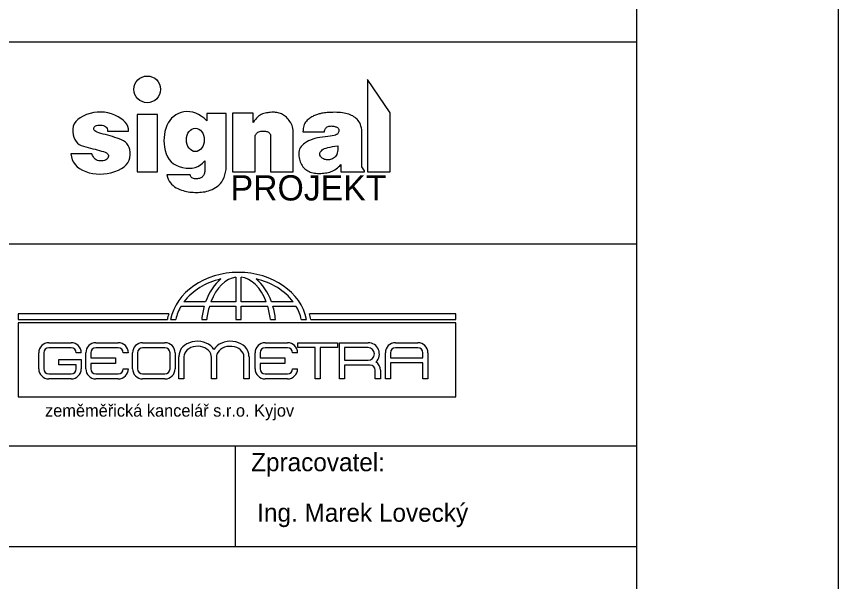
# Model space of a CAD drawing. Extents: x 1983 to 3683, y -1637 to -1193.
# Drawn here: x 2856.3 to 2937.6, y -1538.2 to -1482.2 of the extents above; entities that cross this region are included whole.
import ezdxf

# ---------------------------------------------------------------- set-up
doc = ezdxf.new("R2010")
doc.units = 0
for name, color, linetype in [('Default', 7, 'Continuous'), ('Komunikace', 7, 'Continuous'), ('Křížky', 7, 'Continuous'), ('Svazek obcí-chráničky', 7, 'Continuous'), ('Vrstva 51', 7, 'Continuous')]:
    doc.layers.add(name, color=color, linetype=linetype)

msp = doc.modelspace()

# ---------------------------------------------------------------- linework, layer by layer
at = {"layer": 'Default'}
msp.add_lwpolyline([(2727.602, -1636.746), (2937.602, -1636.746), (2937.602, -1339.746), (2727.602, -1339.746)], close=True, dxfattribs=at)
at = {"layer": 'Komunikace'}
for points in [[(2893.266, -1497.626), (2893.266, -1491.786), (2891.026, -1488.506), (2891.026, -1497.626), (2893.266, -1497.626)], [(2864.538, -1497.86), (2864.9, -1497.844), (2865.266, -1497.796), (2865.637, -1497.717), (2866.013, -1497.607), (2866.368, -1497.471), (2866.676, -1497.315), (2866.937, -1497.139), (2867.151, -1496.943), (2867.318, -1496.727), (2867.439, -1496.491), (2867.512, -1496.235), (2867.539, -1495.959), (2867.528, -1495.685), (2867.49, -1495.437), (2867.424, -1495.212), (2867.33, -1495.013), (2867.209, -1494.838), (2867.059, -1494.688), (2866.882, -1494.563), (2866.678, -1494.462), (2866.458, -1494.376), (2866.236, -1494.294), (2866.012, -1494.217), (2865.786, -1494.144), (2865.557, -1494.075), (2865.326, -1494.011), (2865.092, -1493.952), (2864.857, -1493.896), (2864.635, -1493.841), (2864.444, -1493.782), (2864.283, -1493.719), (2864.153, -1493.652), (2864.053, -1493.581), (2863.983, -1493.506), (2863.944, -1493.427), (2863.936, -1493.343), (2863.952, -1493.264), (2863.989, -1493.195), (2864.045, -1493.137), (2864.121, -1493.09), (2864.217, -1493.053), (2864.332, -1493.028), (2864.468, -1493.013), (2864.623, -1493.01), (2864.778, -1493.021), (2864.914, -1493.05), (2865.029, -1493.097), (2865.123, -1493.163), (2865.198, -1493.247), (2865.253, -1493.349), (2865.287, -1493.469), (2865.302, -1493.608), (2867.381, -1493.608), (2867.361, -1493.366), (2867.299, -1493.136), (2867.194, -1492.919), (2867.046, -1492.715), (2866.856, -1492.523), (2866.622, -1492.345), (2866.345, -1492.179), (2866.026, -1492.025), (2865.684, -1491.896), (2865.339, -1491.801), (2864.991, -1491.741), (2864.641, -1491.717), (2864.288, -1491.727), (2863.932, -1491.771), (2863.574, -1491.851), (2863.213, -1491.966), (2862.875, -1492.108), (2862.586, -1492.271), (2862.345, -1492.454), (2862.153, -1492.658), (2862.009, -1492.882), (2861.915, -1493.127), (2861.868, -1493.393), (2861.871, -1493.679), (2861.91, -1493.96), (2861.976, -1494.212), (2862.069, -1494.434), (2862.187, -1494.627), (2862.332, -1494.791), (2862.503, -1494.924), (2862.7, -1495.029), (2862.923, -1495.103), (2863.158, -1495.163), (2863.389, -1495.223), (2863.617, -1495.282), (2863.841, -1495.341), (2864.061, -1495.4), (2864.278, -1495.458), (2864.491, -1495.516), (2864.701, -1495.574), (2864.893, -1495.634), (2865.054, -1495.698), (2865.185, -1495.767), (2865.284, -1495.841), (2865.353, -1495.918), (2865.391, -1496.001), (2865.398, -1496.088), (2865.374, -1496.179), (2865.327, -1496.267), (2865.266, -1496.343), (2865.191, -1496.408), (2865.101, -1496.461), (2864.997, -1496.503), (2864.878, -1496.533), (2864.745, -1496.551), (2864.598, -1496.558), (2864.45, -1496.547), (2864.314, -1496.514), (2864.19, -1496.458), (2864.079, -1496.38), (2863.98, -1496.279), (2863.894, -1496.155), (2863.82, -1496.008), (2863.758, -1495.84), (2861.678, -1495.84), (2861.722, -1496.147), (2861.805, -1496.429), (2861.928, -1496.687), (2862.091, -1496.92), (2862.293, -1497.13), (2862.535, -1497.315), (2862.816, -1497.476), (2863.137, -1497.613), (2863.48, -1497.722), (2863.828, -1497.799), (2864.181, -1497.846), (2864.538, -1497.86)], [(2870.226, -1497.626), (2870.226, -1491.946), (2868.226, -1491.946), (2868.226, -1497.626), (2870.226, -1497.626)], [(2874.086, -1499.668), (2874.254, -1499.664), (2874.424, -1499.656), (2874.596, -1499.642), (2874.77, -1499.624), (2874.944, -1499.597), (2875.118, -1499.558), (2875.292, -1499.507), (2875.465, -1499.443), (2875.638, -1499.368), (2875.811, -1499.28), (2875.984, -1499.181), (2876.156, -1499.069), (2876.32, -1498.939), (2876.469, -1498.786), (2876.601, -1498.611), (2876.718, -1498.412), (2876.819, -1498.19), (2876.904, -1497.945), (2876.973, -1497.677), (2877.026, -1497.386), (2877.026, -1491.866), (2875.106, -1491.866), (2875.106, -1492.586), (2874.84, -1492.331), (2874.57, -1492.118), (2874.295, -1491.946), (2874.016, -1491.815), (2873.733, -1491.725), (2873.446, -1491.676), (2873.154, -1491.669), (2872.858, -1491.702), (2872.571, -1491.77), (2872.306, -1491.867), (2872.062, -1491.992), (2871.84, -1492.146), (2871.64, -1492.329), (2871.462, -1492.539), (2871.306, -1492.779), (2871.171, -1493.047), (2871.06, -1493.333), (2870.975, -1493.626), (2870.916, -1493.926), (2870.883, -1494.233), (2870.876, -1494.548), (2870.895, -1494.869), (2870.94, -1495.198), (2871.011, -1495.534), (2871.111, -1495.858), (2871.243, -1496.148), (2871.409, -1496.406), (2871.607, -1496.632), (2871.838, -1496.825), (2872.101, -1496.985), (2872.397, -1497.112), (2872.726, -1497.207), (2873.062, -1497.265), (2873.381, -1497.282), (2873.681, -1497.259), (2873.964, -1497.195), (2874.229, -1497.09), (2874.477, -1496.944), (2874.707, -1496.758), (2874.918, -1496.531), (2874.918, -1497.608), (2874.9, -1497.696), (2874.877, -1497.777), (2874.849, -1497.853), (2874.817, -1497.923), (2874.781, -1497.988), (2874.74, -1498.047), (2874.694, -1498.1), (2874.644, -1498.147), (2874.588, -1498.189), (2874.526, -1498.225), (2874.456, -1498.256), (2874.379, -1498.281), (2874.295, -1498.302), (2874.204, -1498.316), (2874.106, -1498.326), (2874.001, -1498.33), (2873.897, -1498.324), (2873.804, -1498.306), (2873.72, -1498.274), (2873.647, -1498.229), (2873.584, -1498.171), (2873.532, -1498.099), (2873.489, -1498.014), (2873.457, -1497.916), (2871.15, -1497.916), (2871.219, -1498.144), (2871.302, -1498.352), (2871.399, -1498.542), (2871.51, -1498.714), (2871.635, -1498.867), (2871.773, -1499), (2871.926, -1499.116), (2872.092, -1499.212), (2872.264, -1499.295), (2872.435, -1499.369), (2872.604, -1499.435), (2872.772, -1499.492), (2872.938, -1499.54), (2873.103, -1499.58), (2873.266, -1499.611), (2873.428, -1499.634), (2873.59, -1499.65), (2873.753, -1499.66), (2873.919, -1499.667), (2874.086, -1499.668)], [(2883.666, -1497.626), (2883.666, -1493.826), (2883.663, -1493.656), (2883.649, -1493.492), (2883.624, -1493.336), (2883.589, -1493.186), (2883.543, -1493.042), (2883.486, -1492.905), (2883.418, -1492.775), (2883.339, -1492.651), (2883.254, -1492.535), (2883.167, -1492.427), (2883.078, -1492.327), (2882.987, -1492.235), (2882.894, -1492.152), (2882.799, -1492.077), (2882.702, -1492.01), (2882.603, -1491.951), (2882.501, -1491.9), (2882.395, -1491.855), (2882.284, -1491.818), (2882.169, -1491.787), (2882.049, -1491.764), (2881.926, -1491.747), (2881.798, -1491.738), (2881.666, -1491.735), (2881.532, -1491.738), (2881.399, -1491.746), (2881.268, -1491.759), (2881.138, -1491.777), (2881.009, -1491.8), (2880.881, -1491.828), (2880.754, -1491.861), (2880.629, -1491.898), (2880.505, -1491.947), (2880.384, -1492.011), (2880.265, -1492.093), (2880.149, -1492.19), (2880.034, -1492.305), (2879.923, -1492.435), (2879.813, -1492.582), (2879.706, -1492.746), (2879.706, -1491.826), (2877.666, -1491.826), (2877.666, -1497.626), (2879.906, -1497.626), (2879.906, -1494.066), (2879.941, -1493.975), (2879.985, -1493.894), (2880.039, -1493.823), (2880.104, -1493.762), (2880.178, -1493.711), (2880.262, -1493.67), (2880.356, -1493.639), (2880.46, -1493.617), (2880.566, -1493.604), (2880.666, -1493.598), (2880.762, -1493.597), (2880.852, -1493.602), (2880.937, -1493.614), (2881.017, -1493.631), (2881.091, -1493.655), (2881.16, -1493.685), (2881.223, -1493.719), (2881.277, -1493.758), (2881.322, -1493.8), (2881.36, -1493.846), (2881.389, -1493.895), (2881.41, -1493.948), (2881.422, -1494.005), (2881.426, -1494.066), (2881.426, -1497.626), (2883.666, -1497.626)], [(2886.229, -1497.79), (2886.391, -1497.787), (2886.548, -1497.778), (2886.702, -1497.764), (2886.851, -1497.744), (2886.995, -1497.718), (2887.135, -1497.686), (2887.271, -1497.649), (2887.403, -1497.606), (2887.532, -1497.555), (2887.659, -1497.493), (2887.784, -1497.421), (2887.908, -1497.339), (2888.03, -1497.246), (2888.15, -1497.143), (2888.269, -1497.03), (2888.386, -1496.906), (2888.386, -1497.626), (2890.706, -1497.626), (2890.706, -1497.546), (2890.466, -1497.146), (2890.466, -1493.666), (2890.44, -1493.461), (2890.404, -1493.271), (2890.359, -1493.095), (2890.304, -1492.934), (2890.239, -1492.787), (2890.165, -1492.655), (2890.082, -1492.537), (2889.989, -1492.434), (2889.888, -1492.341), (2889.78, -1492.255), (2889.667, -1492.176), (2889.547, -1492.104), (2889.421, -1492.039), (2889.288, -1491.981), (2889.15, -1491.93), (2889.005, -1491.886), (2888.853, -1491.848), (2888.694, -1491.816), (2888.527, -1491.79), (2888.354, -1491.769), (2888.173, -1491.754), (2887.985, -1491.744), (2887.79, -1491.741), (2887.588, -1491.743), (2887.389, -1491.749), (2887.205, -1491.757), (2887.036, -1491.768), (2886.881, -1491.78), (2886.741, -1491.795), (2886.616, -1491.813), (2886.506, -1491.832), (2886.41, -1491.854), (2886.322, -1491.877), (2886.232, -1491.903), (2886.142, -1491.931), (2886.051, -1491.96), (2885.96, -1491.992), (2885.868, -1492.025), (2885.775, -1492.061), (2885.682, -1492.098), (2885.589, -1492.14), (2885.496, -1492.188), (2885.405, -1492.244), (2885.315, -1492.306), (2885.226, -1492.375), (2885.138, -1492.451), (2885.05, -1492.533), (2884.964, -1492.623), (2884.884, -1492.72), (2884.815, -1492.827), (2884.756, -1492.944), (2884.709, -1493.069), (2884.672, -1493.204), (2884.646, -1493.349), (2884.631, -1493.502), (2884.626, -1493.666), (2886.746, -1493.666), (2886.762, -1493.569), (2886.786, -1493.482), (2886.819, -1493.404), (2886.86, -1493.335), (2886.91, -1493.275), (2886.969, -1493.225), (2887.036, -1493.183), (2887.112, -1493.151), (2887.193, -1493.127), (2887.274, -1493.109), (2887.355, -1493.098), (2887.437, -1493.093), (2887.52, -1493.095), (2887.603, -1493.103), (2887.687, -1493.118), (2887.771, -1493.139), (2887.851, -1493.165), (2887.923, -1493.192), (2887.985, -1493.222), (2888.039, -1493.254), (2888.084, -1493.288), (2888.121, -1493.325), (2888.148, -1493.363), (2888.167, -1493.404), (2888.178, -1493.447), (2888.183, -1493.493), (2888.182, -1493.541), (2888.175, -1493.592), (2888.161, -1493.647), (2888.141, -1493.704), (2888.115, -1493.763), (2888.082, -1493.826), (2888.032, -1493.887), (2887.951, -1493.943), (2887.839, -1493.994), (2887.698, -1494.039), (2887.526, -1494.079), (2887.323, -1494.114), (2887.091, -1494.143), (2886.828, -1494.168), (2886.556, -1494.194), (2886.296, -1494.232), (2886.049, -1494.28), (2885.814, -1494.338), (2885.591, -1494.407), (2885.381, -1494.486), (2885.183, -1494.577), (2884.997, -1494.677), (2884.828, -1494.785), (2884.679, -1494.898), (2884.552, -1495.015), (2884.445, -1495.137), (2884.36, -1495.263), (2884.295, -1495.394), (2884.251, -1495.529), (2884.228, -1495.669), (2884.22, -1495.81), (2884.221, -1495.95), (2884.231, -1496.089), (2884.25, -1496.227), (2884.278, -1496.364), (2884.315, -1496.499), (2884.361, -1496.634), (2884.416, -1496.767), (2884.479, -1496.895), (2884.549, -1497.014), (2884.626, -1497.124), (2884.709, -1497.226), (2884.8, -1497.319), (2884.898, -1497.402), (2885.002, -1497.477), (2885.114, -1497.543), (2885.232, -1497.601), (2885.356, -1497.651), (2885.486, -1497.693), (2885.622, -1497.728), (2885.765, -1497.755), (2885.913, -1497.774), (2886.068, -1497.786), (2886.229, -1497.79)], [(2886.945, -1496.445), (2886.842, -1496.425), (2886.747, -1496.396), (2886.66, -1496.36), (2886.581, -1496.317), (2886.511, -1496.266), (2886.448, -1496.206), (2886.393, -1496.14), (2886.346, -1496.065), (2886.312, -1495.987), (2886.294, -1495.911), (2886.293, -1495.835), (2886.308, -1495.759), (2886.341, -1495.685), (2886.39, -1495.612), (2886.456, -1495.54), (2886.538, -1495.468), (2886.642, -1495.4), (2886.77, -1495.337), (2886.924, -1495.279), (2887.103, -1495.227), (2887.307, -1495.18), (2887.537, -1495.138), (2887.791, -1495.101), (2888.071, -1495.07), (2888.075, -1495.268), (2888.067, -1495.45), (2888.045, -1495.616), (2888.01, -1495.766), (2887.963, -1495.9), (2887.902, -1496.017), (2887.829, -1496.119), (2887.743, -1496.204), (2887.649, -1496.275), (2887.554, -1496.334), (2887.457, -1496.382), (2887.358, -1496.418), (2887.257, -1496.442), (2887.155, -1496.455), (2887.051, -1496.456), (2886.945, -1496.445)]]:
    msp.add_lwpolyline(points, dxfattribs=at)
msp.add_circle((2869.226, -1489.466), 1.32, dxfattribs=at)
msp.add_ellipse((2873.986, -1494.466), major_axis=(0, 1.16), ratio=0.758621, dxfattribs=at)
at = {"layer": 'Křížky'}
msp.add_lwpolyline([(2747.602, -1359.746), (2917.602, -1359.746), (2917.602, -1619.746), (2747.602, -1619.746)], close=True, dxfattribs=at)
at = {"layer": 'Svazek obcí-chráničky'}
for p, q in [((2877.997, -1508.059), (2877.997, -1510.505)), ((2878.504, -1510.505), (2878.504, -1508.057)), ((2875.003, -1510.505), (2872.858, -1510.505)), ((2877.997, -1510.505), (2875.52, -1510.505)), ((2880.998, -1510.505), (2878.504, -1510.505)), ((2883.66, -1510.505), (2881.515, -1510.505)), ((2872.583, -1510.916), (2874.871, -1510.916)), ((2875.381, -1510.916), (2877.997, -1510.916)), ((2877.997, -1510.916), (2877.997, -1512.237)), ((2878.504, -1512.237), (2878.504, -1510.916)), ((2878.504, -1510.916), (2881.138, -1510.916)), ((2881.648, -1510.916), (2883.935, -1510.916)), ((2871.352, -1511.706), (2856.472, -1511.706)), ((2856.472, -1511.706), (2856.472, -1512.237)), ((2856.472, -1512.237), (2871.215, -1512.237)), ((2871.54, -1512.237), (2872.057, -1512.237)), ((2874.614, -1512.237), (2875.114, -1512.237)), ((2877.997, -1512.237), (2878.504, -1512.237)), ((2881.405, -1512.237), (2881.905, -1512.237)), ((2884.461, -1512.237), (2884.978, -1512.237)), ((2899.75, -1511.706), (2885.272, -1511.706)), ((2885.41, -1512.237), (2899.75, -1512.237)), ((2899.75, -1512.237), (2899.75, -1511.706)), ((2899.749, -1512.581), (2856.466, -1512.581)), ((2856.466, -1512.581), (2856.466, -1519.919)), ((2899.749, -1519.919), (2899.749, -1512.581)), ((2859.491, -1514.547), (2861.701, -1514.547)), ((2864.147, -1514.547), (2866.358, -1514.547)), ((2868.771, -1514.547), (2870.981, -1514.547)), ((2880.889, -1514.547), (2883.1, -1514.547)), ((2888.227, -1514.547), (2891.071, -1514.547)), ((2893.775, -1514.547), (2895.986, -1514.547)), ((2858.493, -1517.131), (2858.493, -1515.545)), ((2858.992, -1515.545), (2858.992, -1517.131)), ((2861.701, -1515.046), (2859.491, -1515.046)), ((2862.699, -1515.545), (2862.2, -1515.545)), ((2863.149, -1517.131), (2863.149, -1515.545)), ((2863.648, -1515.545), (2863.648, -1516.056)), ((2866.358, -1515.046), (2864.147, -1515.046)), ((2867.355, -1515.545), (2866.857, -1515.545)), ((2867.773, -1517.131), (2867.773, -1515.545)), ((2868.272, -1515.545), (2868.272, -1517.131)), ((2870.981, -1515.046), (2868.771, -1515.046)), ((2871.481, -1517.131), (2871.481, -1515.545)), ((2871.979, -1515.545), (2871.979, -1517.131)), ((2879.892, -1517.131), (2879.892, -1515.545)), ((2880.39, -1515.545), (2880.39, -1516.056)), ((2883.1, -1515.046), (2880.889, -1515.046)), ((2884.098, -1515.545), (2883.599, -1515.545)), ((2885.832, -1518.129), (2885.832, -1515.034)), ((2886.336, -1515.034), (2886.336, -1518.129)), ((2891.071, -1515.036), (2888.731, -1515.036)), ((2888.731, -1515.036), (2888.731, -1516.286)), ((2892.777, -1518.129), (2892.777, -1515.545)), ((2893.276, -1515.545), (2893.276, -1516.054)), ((2895.986, -1515.046), (2893.775, -1515.046)), ((2896.485, -1516.054), (2896.485, -1515.545)), ((2896.983, -1515.545), (2896.983, -1518.129)), ((2860.466, -1516.753), (2860.466, -1516.208)), ((2860.466, -1516.208), (2862.699, -1516.208)), ((2862.699, -1516.208), (2862.699, -1517.131)), ((2863.648, -1516.056), (2866.091, -1516.056)), ((2866.091, -1516.056), (2866.091, -1516.6)), ((2872.352, -1518.129), (2872.352, -1515.944)), ((2872.852, -1515.944), (2872.852, -1518.129)), ((2875.572, -1518.129), (2875.572, -1515.944)), ((2876.072, -1515.944), (2876.072, -1518.129)), ((2878.791, -1518.129), (2878.791, -1515.944)), ((2879.291, -1515.944), (2879.291, -1518.129)), ((2880.39, -1516.056), (2882.833, -1516.056)), ((2882.833, -1516.056), (2882.833, -1516.6)), ((2888.731, -1516.286), (2891.071, -1516.286)), ((2893.276, -1516.054), (2896.485, -1516.054)), ((2862.2, -1516.753), (2860.466, -1516.753)), ((2862.2, -1517.131), (2862.2, -1516.753)), ((2866.091, -1516.6), (2863.648, -1516.6)), ((2863.648, -1516.6), (2863.648, -1517.131)), ((2866.857, -1517.131), (2867.355, -1517.131)), ((2882.833, -1516.6), (2880.39, -1516.6)), ((2880.39, -1516.6), (2880.39, -1517.131)), ((2883.599, -1517.131), (2884.098, -1517.131)), ((2891.071, -1516.775), (2888.731, -1516.775)), ((2891.285, -1516.779), (2891.071, -1516.775)), ((2891.784, -1518.129), (2891.784, -1517.278)), ((2892.283, -1517.278), (2892.283, -1518.129)), ((2896.485, -1516.557), (2893.276, -1516.557)), ((2893.276, -1516.557), (2893.276, -1518.129)), ((2896.485, -1518.129), (2896.485, -1516.557)), ((2859.491, -1517.63), (2861.701, -1517.63)), ((2864.147, -1517.63), (2866.358, -1517.63)), ((2868.771, -1517.63), (2870.981, -1517.63)), ((2880.889, -1517.63), (2883.1, -1517.63)), ((2861.701, -1518.129), (2859.491, -1518.129)), ((2866.358, -1518.129), (2864.147, -1518.129)), ((2870.981, -1518.129), (2868.771, -1518.129)), ((2872.852, -1518.129), (2872.352, -1518.129)), ((2876.072, -1518.129), (2875.572, -1518.129)), ((2879.291, -1518.129), (2878.791, -1518.129)), ((2883.1, -1518.129), (2880.889, -1518.129)), ((2886.336, -1518.129), (2885.832, -1518.129)), ((2892.283, -1518.129), (2891.784, -1518.129)), ((2893.276, -1518.129), (2892.777, -1518.129)), ((2896.983, -1518.129), (2896.485, -1518.129)), ((2856.466, -1519.919), (2899.749, -1519.919))]:
    msp.add_line(p, q, dxfattribs=at)
for points in [[(2885.832, -1515.034), (2884.134, -1515.034), (2884.134, -1514.547), (2888.048, -1514.547)], [(2888.048, -1514.547), (2888.048, -1515.034), (2886.336, -1515.034)], [(2888.731, -1516.775), (2888.731, -1518.129), (2888.227, -1518.129), (2888.227, -1514.547)]]:
    msp.add_lwpolyline(points, dxfattribs=at)
for centre, radius, start, end in [((2859.491, -1515.545), 0.998, 90, 180), ((2861.701, -1515.545), 0.998, 360, 90), ((2864.147, -1515.545), 0.998, 90, 180), ((2866.358, -1515.545), 0.998, 360, 90), ((2868.771, -1515.545), 0.998, 90, 180), ((2870.981, -1515.545), 0.998, 360, 90), ((2880.889, -1515.545), 0.998, 90, 180), ((2883.1, -1515.545), 0.998, 360, 90), ((2891.071, -1515.661), 1.114, 314.45734, 90), ((2893.775, -1515.545), 0.998, 90, 180), ((2895.986, -1515.545), 0.998, 360, 90), ((2859.491, -1515.545), 0.499, 90, 180), ((2861.701, -1515.545), 0.499, 0, 90), ((2864.147, -1515.545), 0.499, 90, 180), ((2866.358, -1515.545), 0.499, 0, 90), ((2868.771, -1515.545), 0.499, 90, 180), ((2870.981, -1515.545), 0.499, 0, 90), ((2874.289, -1515.994), 1.938, 166.96576, 178.52091), ((2874.617, -1516.009), 0.957, 3.86486, 22.41569), ((2877.354, -1515.994), 1.938, 1.47909, 13.03424), ((2880.889, -1515.545), 0.499, 90, 180), ((2883.1, -1515.545), 0.499, 0, 90), ((2891.071, -1515.661), 0.625, 270, 90), ((2893.775, -1515.545), 0.499, 90, 180), ((2895.986, -1515.545), 0.499, 0, 90), ((2877.305, -1516.066), 1.238, 162.61388, 174.3506), ((2891.285, -1517.278), 0.998, 360, 55.44734), ((2859.491, -1517.131), 0.998, 180, 270), ((2859.491, -1517.131), 0.499, 180, 270), ((2861.701, -1517.131), 0.998, 270, 0), ((2861.701, -1517.131), 0.499, 270, 0), ((2864.147, -1517.131), 0.998, 180, 270), ((2864.147, -1517.131), 0.499, 180, 270), ((2866.358, -1517.131), 0.998, 270, 0), ((2866.358, -1517.131), 0.499, 270, 0), ((2868.771, -1517.131), 0.998, 180, 270), ((2868.771, -1517.131), 0.499, 180, 270), ((2870.981, -1517.131), 0.998, 270, 0), ((2870.981, -1517.131), 0.499, 270, 0), ((2880.889, -1517.131), 0.998, 180, 270), ((2880.889, -1517.131), 0.499, 180, 270), ((2883.1, -1517.131), 0.998, 270, 0), ((2883.1, -1517.131), 0.499, 270, 0), ((2891.285, -1517.278), 0.499, 0, 90)]:
    msp.add_arc(centre, radius, start, end, dxfattribs=at)
for centre, major_axis, ratio, start_param, end_param in [((2878.259, -1513.109), (-6.804, 0), 0.811768, 3.300239, 6.124539), ((2878.259, -1513.109), (-6.296, 0), 0.804826, 4.992897, 5.743383), ((2878.259, -1513.109), (0, 5.524), 0.668443, 0.491666, 1.079789), ((2878.259, -1513.109), (0, 5.067), 0.630136, 0.08224, 1.030995), ((2878.259, -1513.109), (0, 5.067), 0.630136, 5.252191, 6.206521), ((2878.259, -1513.109), (0, 5.524), 0.668443, 5.203397, 5.79152), ((2878.259, -1513.109), (-6.296, 0), 0.804826, 3.681394, 4.431881), ((2878.259, -1513.109), (-6.296, 0), 0.804826, 5.835664, 6.110118), ((2878.259, -1513.109), (0, 5.524), 0.668443, 1.16256, 1.41215), ((2878.259, -1513.109), (0, 5.067), 0.630136, 1.123275, 1.397729), ((2878.259, -1513.109), (0, 5.067), 0.630136, 4.885456, 5.159911), ((2878.259, -1513.109), (0, 5.524), 0.668443, 4.871035, 5.120625), ((2878.259, -1513.109), (-6.296, 0), 0.804826, 3.31466, 3.589114), ((2877.933, -1513.109), (-6.804, 0), 0.811768, 6.026233, 6.124539), ((2878.691, -1513.109), (-6.804, 0), 0.811768, 3.300239, 3.398545), ((2874.181, -1515.789), (1.805, 0), 0.766187, 0.429647, 2.97338), ((2874.206, -1515.944), (1.354, 0), 0.766187, 0.29376, 3.141593), ((2877.462, -1515.789), (-1.805, 0), 0.766187, 3.309805, 5.853538), ((2877.437, -1515.944), (-1.354, 0), 0.766187, 3.141593, 6.041607)]:
    msp.add_ellipse(centre, major_axis=major_axis, ratio=ratio, start_param=start_param, end_param=end_param, dxfattribs=at)
at = {"layer": 'Vrstva 51'}
for p, q in [((2747.602, -1504.746), (2917.602, -1504.746)), ((2747.602, -1524.746), (2917.602, -1524.746)), ((2877.952, -1534.746), (2877.952, -1524.746))]:
    msp.add_line(p, q, dxfattribs=at)
msp.add_lwpolyline([(2747.602, -1484.746), (2917.602, -1484.746), (2917.602, -1534.746), (2747.602, -1534.746)], close=True, dxfattribs=at)

# ---------------------------------------------------------------- texts
at = {"layer": 'Komunikace'}
msp.add_text('PROJEKT', height=2.5, dxfattribs=at).set_placement((2877.467, -1500.469))
at = {"layer": 'Svazek obcí-chráničky'}
msp.add_text('zeměměřická kancelář s.r.o. Kyjov', height=1.20984, dxfattribs=at).set_placement((2859.117, -1521.868))
at = {"layer": 'Vrstva 51'}
for s, p in [('Zpracovatel:', (2879.498, -1527.273)), ('Ing. Marek Lovecký', (2880.099, -1532.273))]:
    msp.add_text(s, height=1.8, dxfattribs=at).set_placement(p)

doc.saveas('drawing.dxf')
